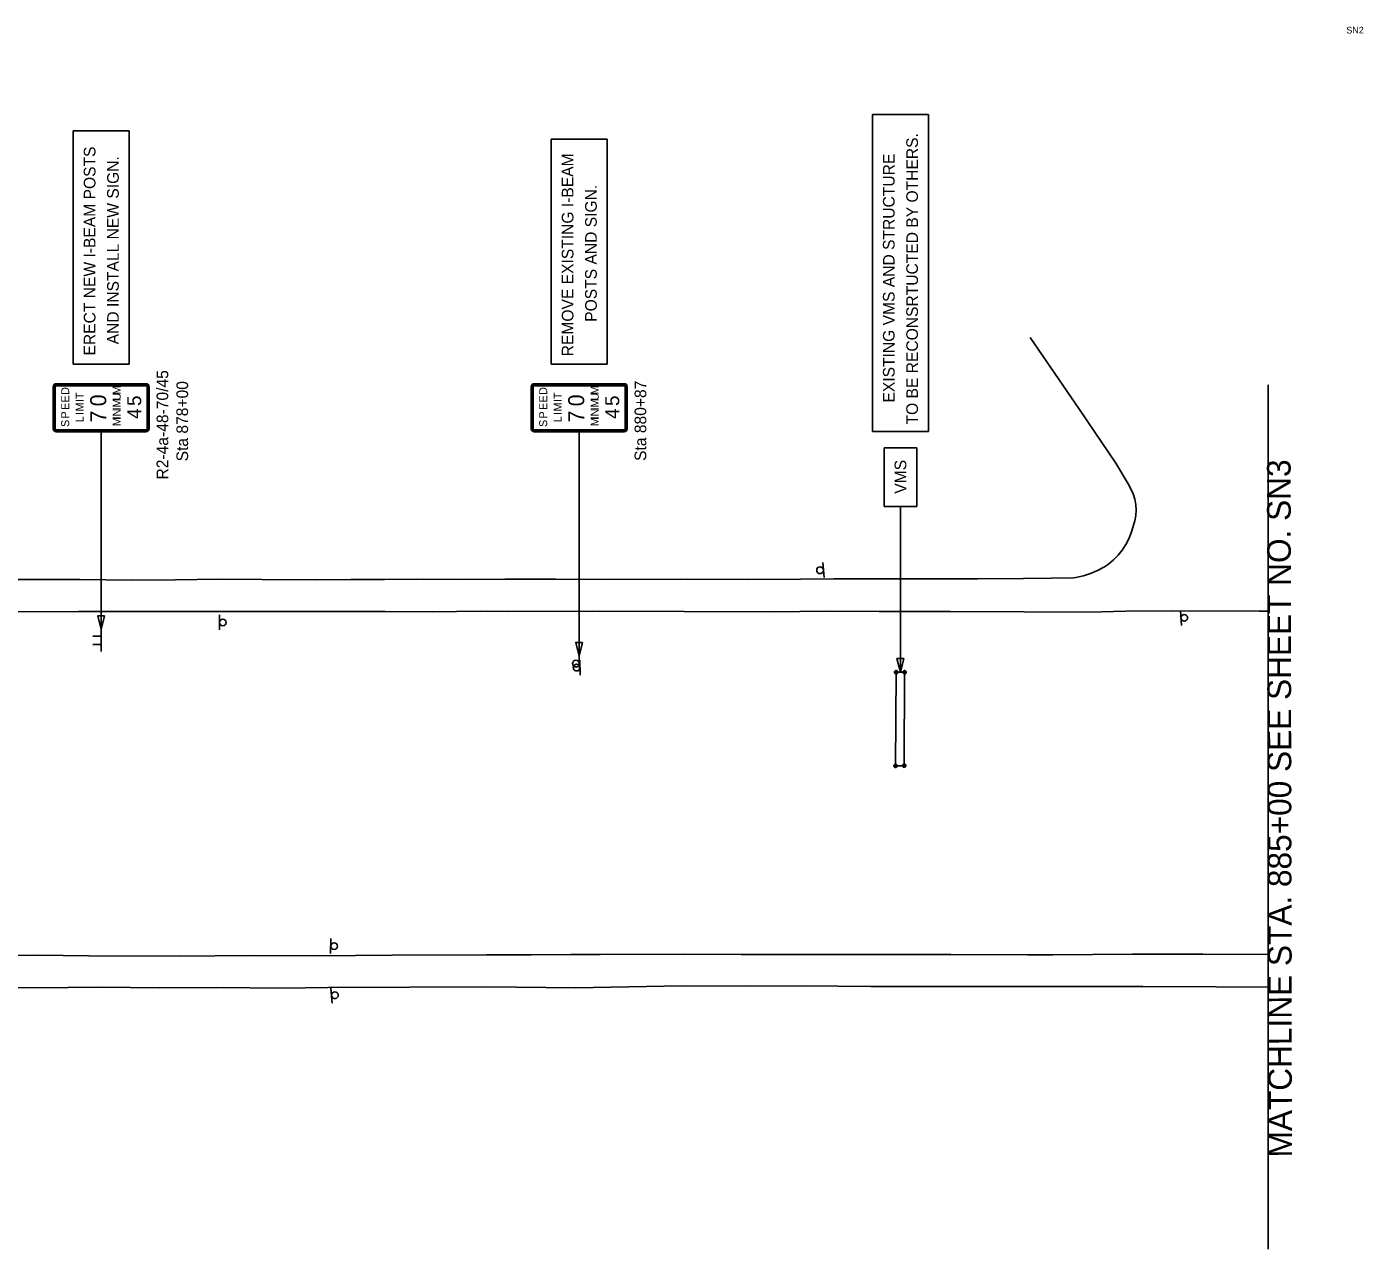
# Model space of a CAD drawing. Extents: x 1738774 to 1740361, y 1164458 to 1165341.
# Drawn here: x 1739559 to 1740361, y 1164608 to 1165341 of the extents above; entities that cross this region are included whole.
import ezdxf

# ---------------------------------------------------------------- set-up
doc = ezdxf.new("R2010")
doc.units = 0
for name, color, linetype in [('RD_EX_Road', 7, 'Continuous'), ('RD_SHT_MatchLine', 7, 'Continuous'), ('RD_SHT_TX', 7, 'Continuous'), ('SN_P_Signs', 7, 'Continuous')]:
    doc.layers.add(name, color=color, linetype=linetype)

msp = doc.modelspace()

# ---------------------------------------------------------------- linework, layer by layer
at = {"layer": 'RD_EX_Road'}
for points in [[(1740161.01, 1165155.08), (1740190.61, 1165111.89), (1740212.45, 1165079.58), (1740219.74, 1165067.18), (1740221.42, 1165064.32), (1740222.75, 1165061.29), (1740223.72, 1165058.11), (1740224.3, 1165054.85), (1740224.49, 1165051.54), (1740224.28, 1165048.23), (1740223.68, 1165044.96), (1740222.7, 1165041.8), (1740222.68, 1165041.73), (1740221.6, 1165037.95), (1740220.15, 1165034.29), (1740218.34, 1165030.8), (1740216.19, 1165027.51), (1740213.71, 1165024.45), (1740210.95, 1165021.65), (1740207.92, 1165019.14), (1740205.49, 1165017.46), (1740201.45, 1165015.32), (1740197.25, 1165013.54), (1740192.91, 1165012.13), (1740188.46, 1165011.09), (1740186.92, 1165010.83), (1740173.59, 1165010.58), (1740157.06, 1165010.44), (1740129.6, 1165010.17), (1740086.32, 1165010.3), (1740043.18, 1165010.23), (1740023.31, 1165010.02), (1739991.93, 1165009.91), (1739951.35, 1165010.09), (1739906.38, 1165009.79), (1739876.34, 1165010.03), (1739845.87, 1165010.14), (1739817.63, 1165009.91), (1739796.89, 1165009.99), (1739773.67, 1165009.84), (1739753.42, 1165009.8), (1739732.24, 1165009.67), (1739700.14, 1165009.84), (1739674.03, 1165010.02), (1739648.4, 1165009.64), (1739622.41, 1165009.51), (1739590.92, 1165009.82), (1739543.17, 1165009.96)], [(1739533.97, 1164990.4), (1739590.03, 1164990.67), (1739623.09, 1164990.71), (1739671.86, 1164990.67), (1739704.82, 1164990.59), (1739735.83, 1164990.66), (1739774.08, 1164990.65), (1739802.44, 1164990.5), (1739831.36, 1164990.8), (1739847.17, 1164990.73), (1739898.64, 1164990.87), (1739953.38, 1164990.64), (1740004.43, 1164990.51), (1740041.27, 1164990.87), (1740070.48, 1164990.6), (1740112.98, 1164990.65), (1740157.39, 1164990.42), (1740196.39, 1164990.29), (1740218.31, 1164990.91), (1740245.76, 1164991.1), (1740298.39, 1164990.84), (1740303.73, 1164990.9)], [(1739538.11, 1164784.14), (1739565.64, 1164784.49), (1739596.21, 1164784.22), (1739651.11, 1164784.02), (1739692.95, 1164784.25), (1739734.28, 1164784.23), (1739778.36, 1164784.56), (1739834.92, 1164784.66), (1739861.63, 1164784.72), (1739885.5, 1164784.9), (1739902.99, 1164784.87), (1739953.78, 1164785.18), (1739987.62, 1164784.96), (1740039.51, 1164784.98), (1740074.18, 1164784.97), (1740113.36, 1164784.87), (1740159.29, 1164784.74), (1740174.59, 1164784.72), (1740222.45, 1164785.22), (1740264.59, 1164785.18), (1740303.73, 1164784.87)], [(1739552.94, 1164764.93), (1739583.93, 1164765.19), (1739603.66, 1164765.29), (1739638.77, 1164764.99), (1739673.15, 1164765.18), (1739712.7, 1164764.81), (1739739.74, 1164765.21), (1739788.73, 1164765.36), (1739835.12, 1164765.6), (1739888.23, 1164765), (1739952.02, 1164766.07), (1739990.54, 1164765.96), (1740026.04, 1164766.04), (1740065.4, 1164765.69), (1740094.62, 1164765.8), (1740126.01, 1164765.71), (1740156.99, 1164765.69), (1740228.66, 1164765.82), (1740272.52, 1164765.57), (1740303.73, 1164765.38)]]:
    msp.add_lwpolyline(points, dxfattribs=at)
at = {"layer": 'RD_SHT_MatchLine'}
msp.add_lwpolyline([(1740303.73, 1164608.13), (1740303.73, 1164894.04), (1740303.73, 1165126.71)], dxfattribs=at)
at = {"layer": 'SN_P_Signs'}
for p, q in [((1740066.32, 1165098.72), (1740066.32, 1165288.74)), ((1740066.32, 1165288.74), (1740099.94, 1165288.74)), ((1740099.94, 1165288.74), (1740099.94, 1165098.72)), ((1739586.93, 1165138.99), (1739586.93, 1165279.01)), ((1739586.93, 1165279.01), (1739620.54, 1165279.01)), ((1739620.54, 1165279.01), (1739620.54, 1165138.99)), ((1739873.66, 1165138.99), (1739873.66, 1165274.01)), ((1739873.66, 1165274.01), (1739907.28, 1165274.01)), ((1739907.28, 1165274.01), (1739907.28, 1165138.99)), ((1739620.54, 1165138.99), (1739586.93, 1165138.99)), ((1739907.28, 1165138.99), (1739873.66, 1165138.99)), ((1739576.73, 1165127.29), (1739630.73, 1165127.29)), ((1739863.47, 1165127.29), (1739917.47, 1165127.29)), ((1739574.93, 1165100.29), (1739574.93, 1165125.49)), ((1739632.53, 1165125.49), (1739632.53, 1165100.29)), ((1739861.67, 1165100.29), (1739861.67, 1165125.49)), ((1739919.27, 1165125.49), (1739919.27, 1165100.29)), ((1739630.73, 1165098.49), (1739576.73, 1165098.49)), ((1739603.73, 1165098.49), (1739603.73, 1164979.81)), ((1739917.47, 1165098.49), (1739863.47, 1165098.49)), ((1739890.47, 1165098.49), (1739890.47, 1164963.9)), ((1740099.94, 1165098.72), (1740066.32, 1165098.72)), ((1740073.32, 1165053.72), (1740073.32, 1165088.74)), ((1740073.32, 1165088.74), (1740092.94, 1165088.74)), ((1740092.94, 1165088.74), (1740092.94, 1165053.72)), ((1740092.94, 1165053.72), (1740073.32, 1165053.72)), ((1740083.13, 1165053.72), (1740083.13, 1164954.2)), ((1740037.34, 1165011.08), (1740036.54, 1165020.04)), ((1740251.14, 1164991.22), (1740251.73, 1164982.24)), ((1739674.73, 1164988.65), (1739674.68, 1164979.65)), ((1739603.73, 1164975.9), (1739598.74, 1164975.9)), ((1739603.73, 1164979.81), (1739603.73, 1164966.77)), ((1739603.73, 1164970.88), (1739598.74, 1164970.88)), ((1739890.6, 1164954.9), (1739890.47, 1164963.9)), ((1739891.03, 1164952.53), (1739890.89, 1164961.53)), ((1740079.73, 1164953.73), (1740081.48, 1164954.69)), ((1740080.12, 1164955.08), (1740081.09, 1164953.33)), ((1740084.77, 1164953.72), (1740086.52, 1164954.68)), ((1740085.16, 1164955.07), (1740086.13, 1164953.33)), ((1740079.39, 1164897.58), (1740081.13, 1164898.55)), ((1740079.78, 1164898.94), (1740080.74, 1164897.19)), ((1740084.57, 1164897.71), (1740086.32, 1164898.67)), ((1740084.96, 1164899.06), (1740085.93, 1164897.31)), ((1739741.58, 1164794.53), (1739741.36, 1164785.54)), ((1739741.53, 1164764.79), (1739742.35, 1164755.83))]:
    msp.add_line(p, q, dxfattribs=at)
for points in [[(1739576.73, 1165126.84), (1739630.73, 1165126.84)], [(1739863.47, 1165126.84), (1739917.47, 1165126.84)], [(1739575.38, 1165100.29), (1739575.38, 1165125.49)], [(1739576.13, 1165100.29), (1739576.13, 1165125.49)], [(1739576.73, 1165126.09), (1739630.73, 1165126.09)], [(1739631.33, 1165125.49), (1739631.33, 1165100.29)], [(1739632.08, 1165125.49), (1739632.08, 1165100.29)], [(1739862.12, 1165100.29), (1739862.12, 1165125.49)], [(1739862.87, 1165100.29), (1739862.87, 1165125.49)], [(1739863.47, 1165126.09), (1739917.47, 1165126.09)], [(1739918.07, 1165125.49), (1739918.07, 1165100.29)], [(1739918.82, 1165125.49), (1739918.82, 1165100.29)], [(1739630.73, 1165099.69), (1739576.73, 1165099.69)], [(1739630.73, 1165098.94), (1739576.73, 1165098.94)], [(1739917.47, 1165099.69), (1739863.47, 1165099.69)], [(1739917.47, 1165098.94), (1739863.47, 1165098.94)], [(1740080.33, 1164953.25), (1740080.17, 1164953.31), (1740080.03, 1164953.39), (1740079.9, 1164953.5), (1740079.79, 1164953.63), (1740079.71, 1164953.77), (1740079.65, 1164953.93), (1740079.61, 1164954.09), (1740079.61, 1164954.26), (1740079.63, 1164954.42), (1740079.68, 1164954.58), (1740079.75, 1164954.73), (1740079.85, 1164954.86), (1740079.97, 1164954.98), (1740080.11, 1164955.08), (1740080.26, 1164955.15), (1740080.42, 1164955.19), (1740080.59, 1164955.21), (1740080.75, 1164955.2), (1740080.88, 1164955.17)], [(1740080.26, 1164898.06), (1740080.61, 1164954.21), (1740085.65, 1164954.2), (1740085.44, 1164898.19), (1740080.26, 1164898.06)], [(1740080.88, 1164955.17), (1740081.04, 1164955.11), (1740081.18, 1164955.03), (1740081.31, 1164954.92), (1740081.42, 1164954.79), (1740081.51, 1164954.65), (1740081.57, 1164954.49), (1740081.6, 1164954.33), (1740081.61, 1164954.16), (1740081.58, 1164954), (1740081.54, 1164953.84), (1740081.46, 1164953.69), (1740081.36, 1164953.55), (1740081.24, 1164953.44), (1740081.11, 1164953.34), (1740080.95, 1164953.27), (1740080.79, 1164953.23), (1740080.63, 1164953.21), (1740080.46, 1164953.22), (1740080.33, 1164953.25)], [(1740085.37, 1164953.24), (1740085.21, 1164953.3), (1740085.07, 1164953.38), (1740084.94, 1164953.49), (1740084.83, 1164953.62), (1740084.75, 1164953.76), (1740084.69, 1164953.92), (1740084.65, 1164954.08), (1740084.65, 1164954.25), (1740084.67, 1164954.41), (1740084.72, 1164954.57), (1740084.79, 1164954.72), (1740084.89, 1164954.86), (1740085.01, 1164954.97), (1740085.15, 1164955.07), (1740085.3, 1164955.14), (1740085.46, 1164955.18), (1740085.63, 1164955.2), (1740085.79, 1164955.19), (1740085.92, 1164955.16)], [(1740085.92, 1164955.16), (1740086.08, 1164955.1), (1740086.22, 1164955.02), (1740086.35, 1164954.91), (1740086.46, 1164954.78), (1740086.55, 1164954.64), (1740086.61, 1164954.48), (1740086.64, 1164954.32), (1740086.65, 1164954.15), (1740086.62, 1164953.99), (1740086.57, 1164953.83), (1740086.5, 1164953.68), (1740086.4, 1164953.54), (1740086.28, 1164953.43), (1740086.14, 1164953.33), (1740085.99, 1164953.26), (1740085.83, 1164953.22), (1740085.67, 1164953.2), (1740085.5, 1164953.21), (1740085.37, 1164953.24)], [(1740079.98, 1164897.1), (1740079.83, 1164897.16), (1740079.68, 1164897.25), (1740079.56, 1164897.35), (1740079.45, 1164897.48), (1740079.36, 1164897.62), (1740079.3, 1164897.78), (1740079.27, 1164897.94), (1740079.26, 1164898.11), (1740079.28, 1164898.28), (1740079.33, 1164898.43), (1740079.41, 1164898.58), (1740079.51, 1164898.72), (1740079.62, 1164898.84), (1740079.76, 1164898.93), (1740079.91, 1164899), (1740080.07, 1164899.05), (1740080.24, 1164899.06), (1740080.41, 1164899.05), (1740080.54, 1164899.02)], [(1740080.54, 1164899.02), (1740080.69, 1164898.96), (1740080.84, 1164898.88), (1740080.97, 1164898.77), (1740081.07, 1164898.65), (1740081.16, 1164898.5), (1740081.22, 1164898.35), (1740081.25, 1164898.18), (1740081.26, 1164898.02), (1740081.24, 1164897.85), (1740081.19, 1164897.69), (1740081.11, 1164897.54), (1740081.01, 1164897.41), (1740080.9, 1164897.29), (1740080.76, 1164897.2), (1740080.61, 1164897.13), (1740080.45, 1164897.08), (1740080.28, 1164897.06), (1740080.11, 1164897.07), (1740079.98, 1164897.1)], [(1740085.17, 1164897.23), (1740085.01, 1164897.29), (1740084.87, 1164897.37), (1740084.74, 1164897.48), (1740084.63, 1164897.6), (1740084.54, 1164897.75), (1740084.48, 1164897.9), (1740084.45, 1164898.07), (1740084.44, 1164898.23), (1740084.47, 1164898.4), (1740084.52, 1164898.56), (1740084.59, 1164898.71), (1740084.69, 1164898.84), (1740084.81, 1164898.96), (1740084.95, 1164899.05), (1740085.1, 1164899.13), (1740085.26, 1164899.17), (1740085.42, 1164899.19), (1740085.59, 1164899.18), (1740085.72, 1164899.15)], [(1740085.72, 1164899.15), (1740085.88, 1164899.09), (1740086.02, 1164899), (1740086.15, 1164898.9), (1740086.26, 1164898.77), (1740086.34, 1164898.63), (1740086.4, 1164898.47), (1740086.44, 1164898.31), (1740086.44, 1164898.14), (1740086.42, 1164897.98), (1740086.37, 1164897.82), (1740086.3, 1164897.67), (1740086.2, 1164897.53), (1740086.08, 1164897.42), (1740085.94, 1164897.32), (1740085.79, 1164897.25), (1740085.63, 1164897.21), (1740085.46, 1164897.19), (1740085.3, 1164897.2), (1740085.17, 1164897.23)]]:
    msp.add_lwpolyline(points, dxfattribs=at)
for points in [[(1739605.79, 1164988.01), (1739603.73, 1164979.81), (1739601.68, 1164988.01)], [(1739892.52, 1164972.11), (1739890.47, 1164963.9), (1739888.42, 1164972.11)], [(1740085.18, 1164962.41), (1740083.13, 1164954.2), (1740081.08, 1164962.41)]]:
    msp.add_lwpolyline(points, close=True, dxfattribs=at)
for centre in [(1740034.92, 1165015.4), (1739676.73, 1164984.12), (1740253.45, 1164986.85), (1739888.51, 1164959.39), (1739888.94, 1164957.01), (1739743.49, 1164789.97), (1739743.96, 1164760.47)]:
    msp.add_circle(centre, 2, dxfattribs=at)
for centre, radius, start, end in [((1739576.73, 1165125.49), 1.8, 90, 180), ((1739576.73, 1165125.49), 1.35, 90, 180), ((1739630.73, 1165125.49), 1.8, 0, 90), ((1739630.73, 1165125.49), 1.35, 0, 90), ((1739863.47, 1165125.49), 1.8, 90, 180), ((1739863.47, 1165125.49), 1.35, 90, 180), ((1739917.47, 1165125.49), 1.8, 0, 90), ((1739917.47, 1165125.49), 1.35, 0, 90), ((1739576.73, 1165125.49), 0.6, 90, 180), ((1739630.73, 1165125.49), 0.6, 0, 90), ((1739863.47, 1165125.49), 0.6, 90, 180), ((1739917.47, 1165125.49), 0.6, 0, 90), ((1739576.73, 1165100.29), 1.8, 180, 270), ((1739576.73, 1165100.29), 1.35, 180, 270), ((1739576.73, 1165100.29), 0.6, 180, 270), ((1739630.73, 1165100.29), 0.6, 270, 0), ((1739630.73, 1165100.29), 1.35, 270, 0), ((1739630.73, 1165100.29), 1.8, 270, 0), ((1739863.47, 1165100.29), 1.8, 180, 270), ((1739863.47, 1165100.29), 1.35, 180, 270), ((1739863.47, 1165100.29), 0.6, 180, 270), ((1739917.47, 1165100.29), 0.6, 270, 0), ((1739917.47, 1165100.29), 1.35, 270, 0), ((1739917.47, 1165100.29), 1.8, 270, 0)]:
    msp.add_arc(centre, radius, start, end, dxfattribs=at)

# ---------------------------------------------------------------- texts
at = {"layer": 'RD_SHT_TX'}
msp.add_text('SN2', height=4, dxfattribs=at).set_placement((1740350.67, 1165337.36))
msp.add_text('MATCHLINE STA. 885+00 SEE SHEET NO. SN3', height=14.1726, rotation=90.11236, dxfattribs=at).set_placement((1740318.05, 1164663.23))
at = {"layer": 'SN_P_Signs'}
for s, height, rotation, p in [('TO BE RECONSRTUCTED BY OTHERS.', 6.9998, 90.00008, (1740093.68, 1165102.85)), ('ERECT NEW I-BEAM POSTS', 6.9998, 90.00008, (1739600.29, 1165144.22)), ('AND INSTALL NEW SIGN.', 6.9998, 90.00008, (1739614.29, 1165150.91)), ('REMOVE EXISTING I-BEAM', 6.9998, 90.00008, (1739887.02, 1165143.73)), ('EXISTING VMS AND STRUCTURE', 6.9998, 90.00008, (1740079.68, 1165116)), ('POSTS AND SIGN.', 6.9998, 90.00008, (1739901.02, 1165164.44)), ('R2-4a-48-70/45', 7, 90.00008, (1739643.95, 1165069.85)), ('Sta 878+00', 7, 90.00008, (1739655.85, 1165080.71)), ('Sta 880+87', 7, 90.00008, (1739930.69, 1165080.98)), ('D', 4.8, 90, (1739584.53, 1165120.63)), ('E', 4.8, 90, (1739584.53, 1165116.08)), ('T', 4.8, 90, (1739593.23, 1165118.16)), ('0', 9.6, 90, (1739606.73, 1165113.73)), ('M', 4.8, 90, (1739615.43, 1165120.78)), ('U', 4.8, 90, (1739615.43, 1165117.15)), ('5', 8.4, 90, (1739627.73, 1165113.94)), ('D', 4.8, 90, (1739871.27, 1165120.63)), ('E', 4.8, 90, (1739871.27, 1165116.08)), ('T', 4.8, 90, (1739879.97, 1165118.16)), ('0', 9.6, 90, (1739893.47, 1165113.73)), ('M', 4.8, 90, (1739902.17, 1165120.78)), ('U', 4.8, 90, (1739902.17, 1165117.15)), ('5', 8.4, 90, (1739914.47, 1165113.94)), ('E', 4.8, 90, (1739584.53, 1165111.54)), ('I', 4.8, 90, (1739593.23, 1165116.34)), ('M', 4.8, 90, (1739593.23, 1165110.68)), ('7', 9.6, 90, (1739606.73, 1165104.11)), ('M', 4.8, 90, (1739615.43, 1165113.02)), ('I', 4.8, 90, (1739615.43, 1165111.34)), ('N', 4.8, 90, (1739615.43, 1165107.7)), ('4', 8.4, 90, (1739627.73, 1165106.2)), ('E', 4.8, 90, (1739871.27, 1165111.54)), ('I', 4.8, 90, (1739879.97, 1165116.34)), ('M', 4.8, 90, (1739879.97, 1165110.68)), ('7', 9.6, 90, (1739893.47, 1165104.11)), ('M', 4.8, 90, (1739902.17, 1165113.02)), ('I', 4.8, 90, (1739902.17, 1165111.34)), ('N', 4.8, 90, (1739902.17, 1165107.7)), ('4', 8.4, 90, (1739914.47, 1165106.2)), ('S', 4.8, 90, (1739584.53, 1165101.34)), ('P', 4.8, 90, (1739584.53, 1165106.44)), ('I', 4.8, 90, (1739593.23, 1165108.62)), ('L', 4.8, 90, (1739593.23, 1165104.11)), ('I', 4.8, 90, (1739615.43, 1165106.02)), ('M', 4.8, 90, (1739615.43, 1165101.89)), ('S', 4.8, 90, (1739871.27, 1165101.34)), ('P', 4.8, 90, (1739871.27, 1165106.44)), ('I', 4.8, 90, (1739879.97, 1165108.62)), ('L', 4.8, 90, (1739879.97, 1165104.11)), ('I', 4.8, 90, (1739902.17, 1165106.02)), ('M', 4.8, 90, (1739902.17, 1165101.89)), ('VMS', 7, 90.00008, (1740086.68, 1165061.33))]:
    msp.add_text(s, height=height, rotation=rotation, dxfattribs=at).set_placement(p)

doc.saveas('drawing.dxf')
